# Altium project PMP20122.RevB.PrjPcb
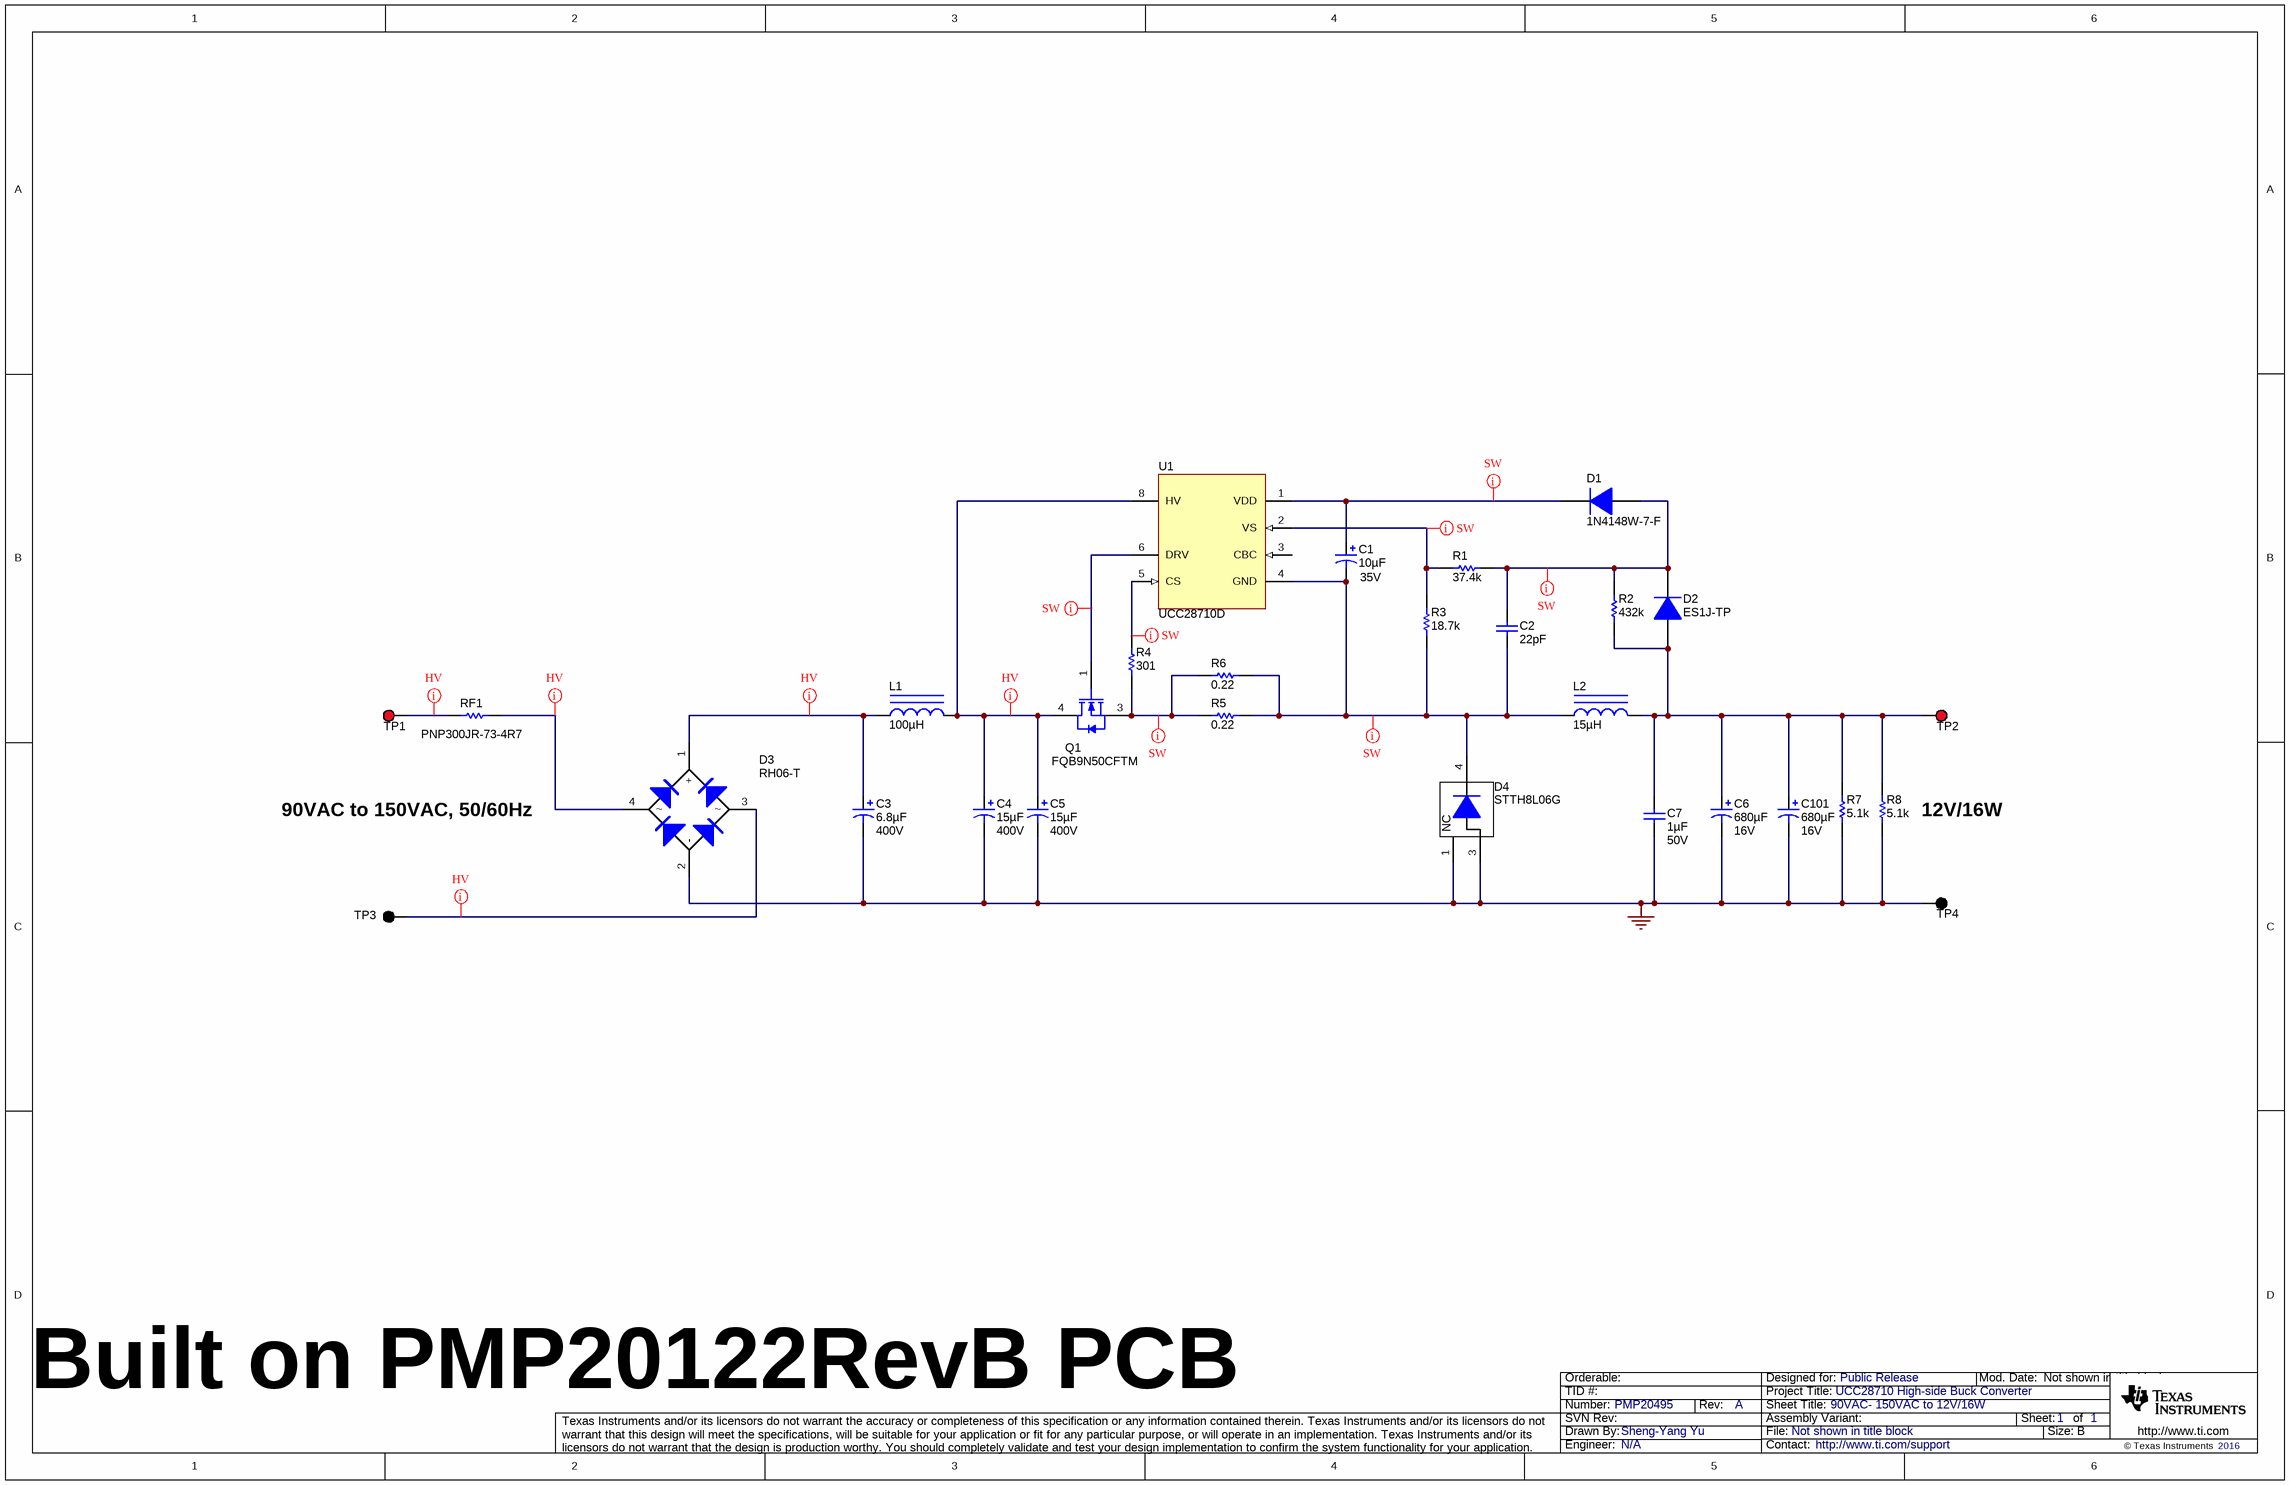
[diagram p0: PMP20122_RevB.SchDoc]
TechSupport: http://www.ti.com/support; SCH_Rev: A; PRJ_Title: UCC28710 High-side Buck Converter; PRJ_Number: PMP20495; PRJ_Engineer: N/A; PRJ_Customer: Public Release; PCB_Rev: B; PCB_Layout: Sheng-Yang Yu; CopyrightYear: 2016
1 sheet, 29 parts. Net scope: global (net labels, ports and power ports of the same name join across sheets).
Board file: PMP20122.RevB_PCB.PcbDoc

## Sheet PMP20122_RevB.SchDoc: 90VAC- 150VAC to 12V/16W
size 431 x 279 mm; Date: Not shown in title block; ApprovedBy: Not shown in title block; CheckedBy: Not shown in title block; Author: Not shown in title block; CompanyName: Not shown in title block; DrawnBy: Sheng-Yang Yu; Engineer: Not shown in title block; Organization: Not shown in title block; Address1: Not shown in title block; Address2: Not shown in title block; Address3: Not shown in title block; Address4: Not shown in title block; DocumentNumber: 1; SheetNumber: 1; SheetTotal: 1; PageSetup: Record=PageOptions¦CenterHorizontal=True¦CenterVertical=True¦PrintScale=1.00¦XCorrection=1.00¦YCorrection=1.00¦PrintKind=0¦BorderSize=5000000¦LeftOffset=0¦BottomOffset=0¦Orientation=2¦PaperLength=1000¦PaperWidth=1000¦Scale=100¦PaperSource=15¦PrintQuality=600¦MediaType=1¦DitherType=10¦PaperKind=Letter¦PrintScaleMode=1

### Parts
C1  ValueDisplayed: 10µF  Value2: 35V  [CAPPR2-5x11]  (hidden comment: UVR1V100MDD1TA)
C2  ValueDisplayed: 22pF  [0603]  (hidden comment: 06035A220JAT2A)
C3  ValueDisplayed: 6.8µF  Value2: 400V  [CAPPRD350W60D800H1100]  (hidden comment: 400AX6R8M8x11)
C4  ValueDisplayed: 15µF  Value2: 400V  [ED_1250x2000]  (hidden comment: EEU-ED2G150)
C5  ValueDisplayed: 15µF  Value2: 400V  [ED_1250x2000]  (hidden comment: EEU-ED2G150)
C6  ValueDisplayed: 680µF  Value2: 16V  [ZL_1000x1600]  (hidden comment: 16ZL680MEFC10X16)
C7  ValueDisplayed: 1µF  Value2: 50V  [0805_HV]  (hidden comment: 08055C105KAT2A)
C101  ValueDisplayed: 680µF  Value2: 16V  [ZL_1000x1600]  (hidden comment: 16ZL680MEFC10X16)
D1  1N4148W-7-F  [SOD-123]
D2  ES1J-TP  [SMA]
D3  RH06-T  [MiniDIP]
D4  STTH8L06G  [DDPAK]
L1  ValueDisplayed: 100µH  [WE-TI_8095]  (hidden comment: 744772101)
L2  ValueDisplayed: 15µH  [WE-HCB_1890]  (hidden comment: 74435571500)
Q1  FQB9N50CFTM  [DDPAK]
R1  ValueDisplayed: 37.4k  [0603]  (hidden comment: CRCW060337K4FKEA)
R2  value 432k  [1206]  (hidden comment: CRCW1206432KFKEA)
R3  value 18.7k  [0603]  (hidden comment: CRCW060318K7FKEA)
R4  value 301  [0603]  (hidden comment: CRCW0603301RFKEA)
R5  ValueDisplayed: 0.22  [1210M]  (hidden comment: MCR25JZHFLR220)
R6  ValueDisplayed: 0.22  [1210M]  (hidden comment: MCR25JZHFLR220)
R7  value 5.1k  [1206]  (hidden comment: CRCW12065K10JNEA)
R8  value 5.1k  [1206]  (hidden comment: CRCW12065K10JNEA)
RF1  PNP300JR-73-4R7  [PNP300]
TP1  5000  [Keystone5000]  (value not drawn)
TP2  5000  [Keystone5000]  (value not drawn)
TP3  5001  [Keystone5001]  (value not drawn)
TP4  5001  [Keystone5001]  (value not drawn)
U1  UCC28710D  [D0007A_N]

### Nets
GND: C3.2(-) C4.2(-) C5.2(-) C6.2(-) C7.2 C101.2(-) D3.2(-) D4.1(NC) D4.3(A) R7.1 R8.1 TP4.1
NetC1_1: C1.1(+) D1.1(K) U1.1(VDD)
NetC1_2: C1.2(-) C2.2 D4.4(K) L2.1 R3.1 R5.2 R6.2 U1.4(GND)
NetC2_1: C2.1 D1.2(A) D2.1(K) R1.1 R2.2
NetC3_1: C3.1(+) D3.1(+) L1.1
NetC4_1: C4.1(+) C5.1(+) L1.2 Q1.4(D) U1.8(HV)
NetC6_1: C6.1(+) C7.1 C101.1(+) D2.2(A) L2.2 R2.1 R7.2 R8.2 TP2.1
NetD3_3: D3.3 TP3.1
NetD3_4: D3.4 RF1.2
NetQ1_1: Q1.1(G) U1.6(DRV)
NetQ1_3: Q1.3(S) R4.1 R5.1 R6.1
NetR1_2: R1.2 R3.2 U1.2(VS)
NetR4_2: R4.2 U1.5(CS)
NetRF1_1: RF1.1 TP1.1

Not connected (* = marked no-connect by the designer): U1 3(CBC)

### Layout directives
net class HV: NetC3_1, NetC4_1, NetD3_3, NetD3_4, NetRF1_1
net class SW: NetC1_1, NetC1_2, NetC2_1, NetQ1_1, NetQ1_3, NetR1_2, NetR4_2

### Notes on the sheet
- 90VAC to 150VAC, 50/60Hz
- (near R8) 12V/16W
- Built on PMP20122RevB PCB

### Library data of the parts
C1 = UVR1V100MDD1TA: CAP, AL, 10uF, 35V, +/-20%, TH; Manufacturer: Nichicon; Polarized: Y; CompType: Capacitor; U/M: EA; Cap_F: 0.00001; Tolerance_%: 20; Value1: Unknown; VDC_V: 35; TaMin_C: -40; TaMax_C: 85; Cap_Case: 5x11
C2 = 06035A220JAT2A: CAP, CERM, 22pF, 50V, +/-5%, C0G/NP0, 0603; Manufacturer: AVX; Polarized: N; CompType: Capacitor; U/M: EA; Cap_F: 0.000000000022; Tolerance_%: 5; ESR_Ohm: 0.259; Value1: 0.259 ohm; VDC_V: 50; TaMin_C: -55; TaMax_C: 125
C3 = 400AX6R8M8x11: CAP, AL, 6.8uF, 400V, +/-20%, TH; Manufacturer: Rubycon; Polarized: Y; CompType: Capacitor; U/M: EA; Cap_F: 0.0000068; Tolerance_%: 20; Value1: Unknown; VDC_V: 400; TaMin_C: -40; TaMax_C: 105; Cap_Case: 8x11
C4 C5 = EEU-ED2G150: CAP, AL, 15 µF, 400 V, +/- 20%, TH; Manufacturer: Panasonic; Polarized: Y; CompType: Capacitor; Value: 15uF; U/M: EA; Cap_F: 0.000015; Tolerance_%: 20; Value1: Unknown; VDC_V: 400; IRMS_A: 0.41; TaMin_C: -25; TaMax_C: 105; Cap_Case: 12.5x20mm; AEC Category: Q200; AEC Qualified: N
C6 C101 = 16ZL680MEFC10X16: CAP, AL, 680 µF, 16 V, +/- 20%, 0.038 ohm, TH; Manufacturer: Rubycon; Polarized: Y; CompType: Capacitor; Value: 680uF; U/M: EA; Cap_F: 0.00068; Tolerance_%: 20; VDC_V: 16; ESR_ohm: 0.038; IRMS_A: 1.43; TaMin_C: -40; TaMax_C: 105; Cap_Case: 10x16mm; AEC Category: Q200; AEC Qualified: N
C7 = 08055C105KAT2A: CAP, CERM, 1uF, 50V, +/-10%, X7R, 0805; Manufacturer: AVX; Polarized: N; CompType: Capacitor; U/M: EA; Cap_F: 0.000001; Tolerance_%: 10; Value1: Unknown; VDC_V: 50; TaMin_C: -55; TaMax_C: 125; Cap_Case: 0805
D1 = 1N4148W-7-F: Diode, Ultrafast, 100V, 0.15A, SOD-123; Manufacturer: Diodes Inc.; U/M: EA; Vf_V: 1.25; Value2: 1.25V; Io_A: 0.15; Vr_V: 100; TJmax_C: 150
D2 = ES1D-13-F: DIODE FAST REC 600V 1A DO214AC; Manufacturer: Diodes Inc.; U/M: EA; Io_A: 1; Vr_V: 600; TJmax_C: 150; RJC_CperW: 25; Type: Ultrafast
D3 = RH06-T: Diode, Switching-Bridge, 600V, 0.5A, MiniDIP; Manufacturer: Diodes Inc.; U/M: EA; Vf_V: 1.15; Value2: 1.15V; Io_A: 0.5; Vr_V: 600; TJmax_C: 150
D4 = STTH8L06G: Diode, Ultrafast, 600 V, 8 A, DDPAK; Manufacturer: STMicroelectronics; SymbolCreator: a0412235; U/M: EA; Vf_V: 0.0875; Value: 600V; Value1: 8A; Value2: 0.0875V; Io_A: 8; Vr_V: 600; TJmax_C: 175; RJC_CperW: 2.5; SizeAreaWB_mm2: 209.6992; SizeArea_mm2: 154.8892; SizeX_mm: 15.245; SizeY_mm: 10.16; SizeZ_mm: 4.445; AEC Category: Q101
L1 = 744772101: Inductor, Unshielded Drum Core, Ferrite, 100 µH, 0.9 A, 0.12 ohm, TH; Manufacturer: Wurth Elektronik; Value: 100uH; Ind_H: 100.0E-6; Imax_A: 0.9; Irms: 0.9A @ 40C rise; Isat: 1.6A @ 10% inductance drop; DCR_ohm: 0.12; Value2: 0.9A; AEC Category: Q200; AEC Qualified: N
L2 = 74435571500: Inductor, Shielded Drum Core, Ferrite, 15 µH, 14 A, 0.009 ohm, SMD; Manufacturer: Wurth Elektronik; Value: 15uH; Ind_H: 15.0E-6; Imax_A: 14; Irms: 14A @ 50C rise; Isat: 14A @ 30% inductance drop; DCR_ohm: 0.009; Value2: 14A; AEC Category: Q200
Q1 = FQB5N50CTM: MOSFET N-CH 500V 9A D2PAK; Manufacturer: Fairchild Semiconductor; Alternate Manufacturer: None; U/M: EA; ChType: N; VdsMax_V: 500; Value1: ? ohm; QgTyp_nC: 18; Vgs_V: 30; IdsMax_A: 5; SizeAreaWB_mm2: 209.6992; SizeArea_mm2: 154.8892; SizeX_mm: 15.245; SizeY_mm: 10.16; SizeZ_mm: 4.445; AEC Category: Q101
R1 = CRCW060337K4FKEA: RES, 37.4 k, 1%, 0.1 W, 0603; Manufacturer: Vishay-Dale; CompType: Resistor; Value: 37.4k; Res_ohm: 37400; Value_Code: 37k4; Tolerance_%: 1; Power_W: 0.1; Value2: 0.1W; VDC_V: 75; TempCo: 100 ppm/C; EIA_Code: E96; U/M: EA; AEC Category: Q200
R2 = CRCW1206432KFKEA: RES, 432k ohm, 1%, 0.25W, 1206; Manufacturer: Vishay-Dale; CompType: Resistor; Res_ohm: 432000; Tolerance_%: 1; Power_W: 0.25; VDC_V: 200; TempCo: 100 ppm/C; EIA_Code: E96; U/M: EA
R3 = CRCW060318K7FKEA: RES, 18.7k ohm, 1%, 0.1W, 0603; Manufacturer: Vishay-Dale; CompType: Resistor; Res_ohm: 18700; Value_Code: 18k7; Tolerance_%: 1; Power_W: 0.1; VDC_V: 75; TempCo: 100 ppm/C; EIA_Code: E96; U/M: EA
R4 = CRCW0603301RFKEA: RES, 301 ohm, 1%, 0.1W, 0603; Manufacturer: Vishay-Dale; CompType: Resistor; Value_Code: 301R; Tolerance_%: 1; Power_W: 0.1; VDC_V: 75; TempCo: 100 ppm/C; EIA_Code: E96; U/M: EA
R5 R6 = MCR25JZHFLR220: RES, 0.22, 1%, 0.5 W, 1210; Manufacturer: Rohm; CompType: Resistor; Value: 0.22; Value_Code: R220; Tolerance_%: 1; Power_W: 0.5; Value2: 0.5W; VDC_V: 0; TempCo: 200 ppm/C; SizeArea_mm2: 8; SizeAreaWB_mm2: 14.7; SizeX_mm: 3.2; SizeY_mm: 2.5; SizeZ_mm: 1.35; EIA_Code: E96; U/M: EA; AEC Category: Q200
R7 R8 = CRCW12065K10JNEA: RES, 5.1k ohm, 5%, 0.25W, 1206; Manufacturer: Vishay-Dale; CompType: Resistor; Res_ohm: 5100; Value_Code: 5k10; Tolerance_%: 5; Power_W: 0.25; VDC_V: 200; TempCo: 200 ppm/C; EIA_Code: E24; U/M: EA
RF1 = PNP300JR-73-4R7: RES, 4.7, 5%, 3 W, 3W Axial resistor; Manufacturer: Yageo America; Value: 4.7; Value_Code: 4R70; Tolerance_%: 5; Power_W: 3; TempCo: 300 ppm/C; EIA_Code: E24; U/M: EA; AEC Category: Q200; AEC Qualified: N
TP1 TP2 = 5000: Test Point, Miniature, Red, TH; Manufacturer: Keystone; CompType: Test Point Loop; U/M: EA
TP3 TP4 = 5001: Test Point, TH, Miniature, Black; Manufacturer: Keystone; Alternate Manufacturer: Any; Alternate PartNumber: Equivalent; CompType: Test Point Loop; U/M: EA
U1 = UCC28710D: Constant-Voltage, Constant-Current Controller With Primary-Side Regulation, D0007A; Alternate Manufacturer: None; Manufacturer: Texas Instruments; SymbolCreator: a0411947; CompType: IC; U/M: EA

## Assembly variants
001: not fitted FID1 FID2 FID3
